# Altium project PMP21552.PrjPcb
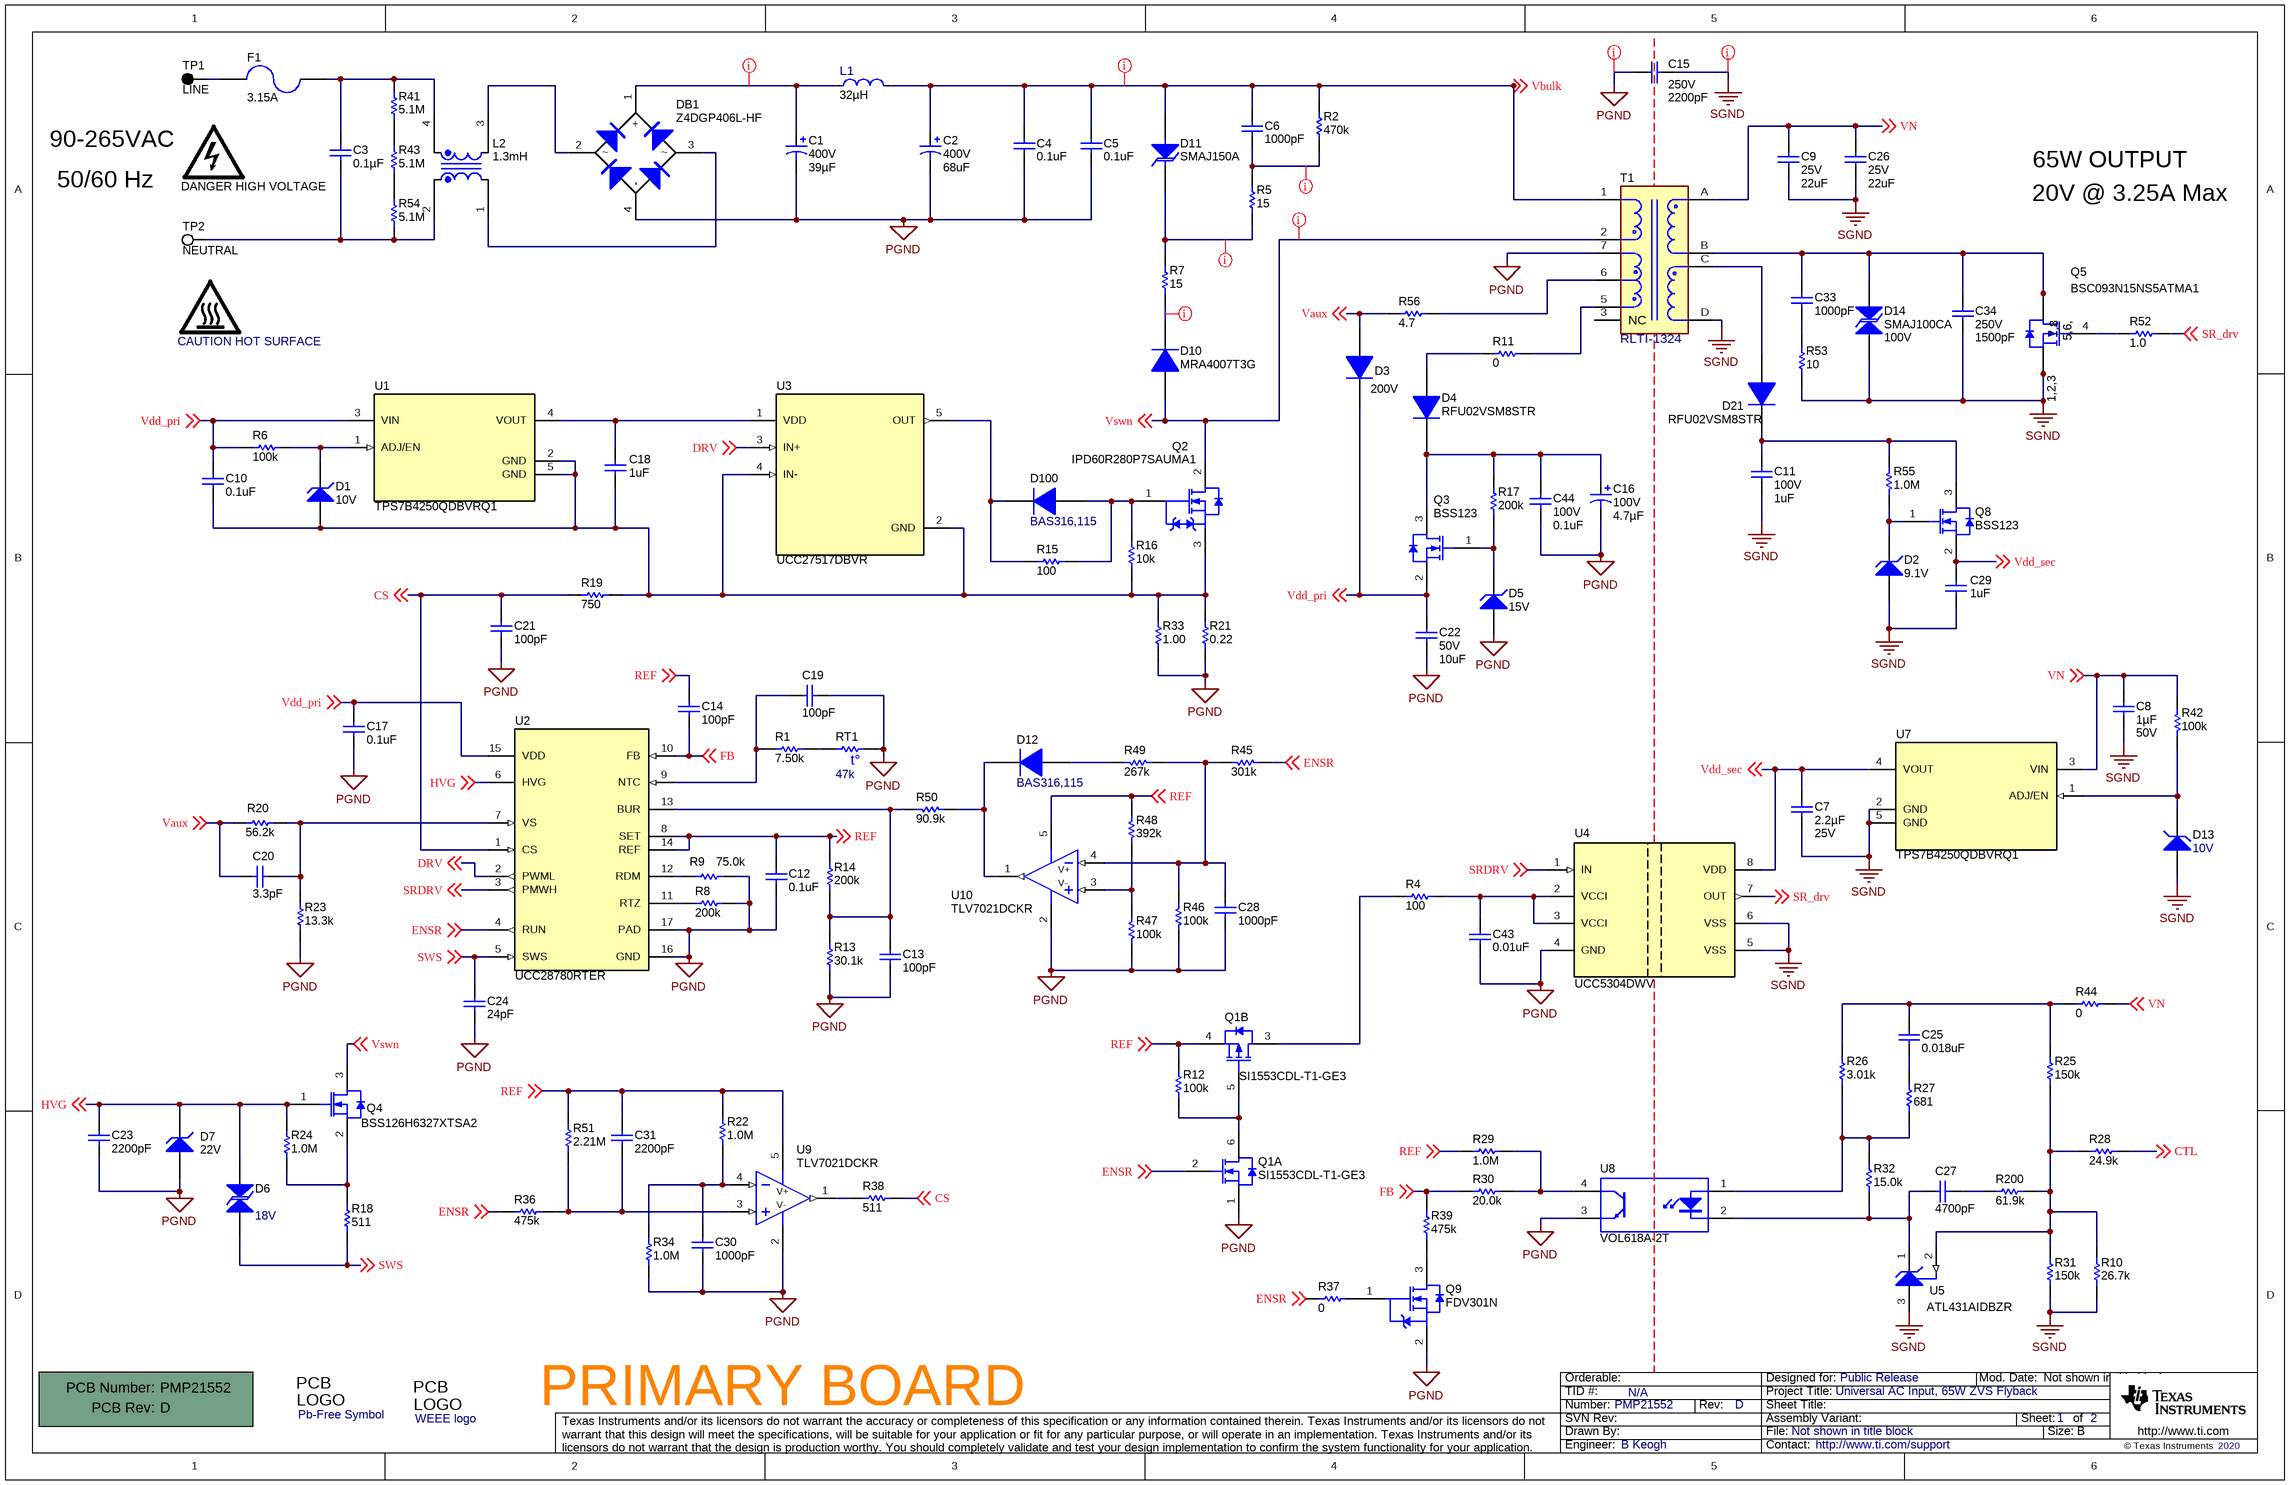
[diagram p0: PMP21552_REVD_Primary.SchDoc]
CopyrightYear: 2020; PCB_Layout: B King; PCB_Rev: D; PRJ_Customer: Public Release; PRJ_Engineer: B Keogh; PRJ_Number: PMP21552; PRJ_Title: Universal AC Input, 65W ZVS Flyback; SCH_Rev: D; TechSupport: http://www.ti.com/support; TID: N/A
2 sheets, 147 parts. Net scope: global (net labels, ports and power ports of the same name join across sheets).
Board file: PMP21552_REVD.PcbDoc
Sheets:
  PMP21552_REVD_Primary.SchDoc
  PMP21552_REVD_Secondary.SchDoc

## Sheet PMP21552_REVD_Primary.SchDoc
size 431 x 279 mm; Date: Not shown in title block; ApprovedBy: Not shown in title block; CheckedBy: Not shown in title block; Author: Not shown in title block; CompanyName: Not shown in title block; Engineer: Not shown in title block; Organization: Not shown in title block; Address1: Not shown in title block; Address2: Not shown in title block; Address3: Not shown in title block; Address4: Not shown in title block; DocumentNumber: 1; Revision: Use project parameter SCH_Rev; SheetNumber: 1; SheetTotal: 2; PageSetup: Record=PageOptions¦CenterHorizontal=True¦CenterVertical=True¦PrintScale=1.00¦XCorrection=1.00¦YCorrection=1.00¦PrintKind=0¦BorderSize=5000000¦LeftOffset=0¦BottomOffset=0¦Orientation=2¦PaperLength=1000¦PaperWidth=1000¦Scale=100¦PaperSource=15¦PrintQuality=600¦MediaType=1¦DitherType=10¦PaperKind=Letter¦PrintScaleMode=1

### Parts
!PCB1  Printed Circuit Board  (value not drawn)  (mechanical)
C1  VDC_V: 400V  ValueDisplayed: 39µF  [Chemi-Con_1450x2000]  (hidden comment: EKXJ401ELL390MU20S)
C2  VDC_V: 400V  ValueDisplayed: 68uF  [BXW_1800x2000]  (hidden comment: 400BXW68MEFC18X20)
C3  ValueDisplayed: 0.1µF  [WCAP-FTX2_1300x700x1300]  (hidden comment: 890324023023)
C4  ValueDisplayed: 0.1uF  [1210_280]  (hidden comment: C1210C104KBRAC7800)
C5  ValueDisplayed: 0.1uF  [1210_280]  (hidden comment: C1210C104KBRAC7800)
C6  ValueDisplayed: 1000pF  [1206L]  (hidden comment: GRM31BR72J102KW01L)
C7  Cap_F: 2.2µF  VDC_V: 25V  [0805_HV1]  (hidden comment: CGA4J3X7R1E225K125AB)
C8  Cap_F: 1µF  VDC_V: 50V  [0805_HV1]  (hidden comment: C2012X7R1H105K085AC)
C9  VDC_V: 25V  ValueDisplayed: 22uF  [1210_270L]  (hidden comment: GRM32ER71E226KE15L)
C10  ValueDisplayed: 0.1uF  [0402S]  (hidden comment: GRM155R71H104ME14D)
C11  VDC_V: 100V  ValueDisplayed: 1uF  [1206L]  (hidden comment: C3216X7R2A105M160AA)
C12  ValueDisplayed: 0.1uF  [0402S]  (hidden comment: C1005X7R1H104K050BB)
C13  ValueDisplayed: 100pF  [0402S]  (hidden comment: GRM1555C1H101JA01D)
C14  ValueDisplayed: 100pF  [0402S]  (hidden comment: GRM1555C1H101JA01D)
C15  VDC_V: 250V  ValueDisplayed: 2200pF  [DE1_900x400]  (hidden comment: DE1E3RA222MN4AN01F)
C16  VDC_V: 100V  ValueDisplayed: 4.7µF  [UPW_500x1100]  (hidden comment: UPS2A4R7MDD1TD)
C17  ValueDisplayed: 0.1uF  [0402S]  (hidden comment: GRM155R71H104ME14D)
C18  ValueDisplayed: 1uF  [0603S]  (hidden comment: C1608X7R1E105K080AB)
C19  ValueDisplayed: 100pF  [0402S]  (hidden comment: GRM1555C1H101JA01D)
C20  ValueDisplayed: 3.3pF  [0402S]  (hidden comment: GRM1555C1H3R3CA01D)
C21  ValueDisplayed: 100pF  [0402S]  (hidden comment: GRM1555C1H101JA01D)
C22  VDC_V: 50V  ValueDisplayed: 10uF  [1206_180]  (hidden comment: C3216X5R1H106K160AB)
C23  ValueDisplayed: 2200pF  [0402S]  (hidden comment: GRM155R71H222KA01D)
C24  ValueDisplayed: 24pF  [0402S]  (hidden comment: GRM1555C1H240JA01D)
C25  ValueDisplayed: 0.018uF  [0402S]  (hidden comment: GRM155R71H183KA12D)
C26  VDC_V: 25V  ValueDisplayed: 22uF  [1210_270L]  (hidden comment: GRM32ER71E226KE15L)
C27  ValueDisplayed: 4700pF  [0402S]  (hidden comment: GRM155R71H472KA01D)
C28  ValueDisplayed: 1000pF  [0402S]  (hidden comment: GRM155R71H102KA01D)
C29  ValueDisplayed: 1uF  [0603S]  (hidden comment: C1608X7R1E105K080AB)
C30  ValueDisplayed: 1000pF  [0402S]  (hidden comment: GRM155R71H102KA01D)
C31  ValueDisplayed: 2200pF  [0402S]  (hidden comment: GRM155R71H222KA01D)
C33  ValueDisplayed: 1000pF  [0805L]  (hidden comment: GRM21AR72E102KW01D)
C34  Value2: 250V  ValueDisplayed: 1500pF  [0805_HV1]  (hidden comment: GRM21AR72E152KW01D)
C43  ValueDisplayed: 0.01uF  [0402S]  (hidden comment: GRM155R71H103KA88D)
C44  VDC_V: 100V  ValueDisplayed: 0.1uF  [1206L]  (hidden comment: 12061C104JAT2A)
D1  value 10V  [SOD-323]  (hidden comment: MMSZ5240BS-7-F)
D2  value 9.1V  [SOD-323]  (hidden comment: BZT52C9V1S-7-F)
D3  value 200V  [SOD-123H]  (hidden comment: CSFMT104-HF)
D4  RFU02VSM8STR  [TUMD2SM]
D5  value 15V  [SOD-323]  (hidden comment: MMSZ5245BS-7-F)
D6  value 18V  [SOD-323-Bi]  (hidden comment: CDSOD323-T18C)
D7  value 22V  [SOD-523]  (hidden comment: BZT52C22T-7)
D10  MRA4007T3G  [SMA]
D11  SMAJ150A  [SMA]
D12  BAS316,115  [SOD-323]
D13  value 10V  [SOD-323]  (hidden comment: MMSZ5240BS-7-F)
D14  SMAJ100CA  value 100V  [SMA]
D21  RFU02VSM8STR  [TUMD2SM]
D100  BAS316,115  [SOD-323]
DB1  Z4DGP406L-HF  [Z4-D]
F1  Irating_A: 3.15A  [FUSE_392]  (hidden comment: 39213150000)
L1  Ind_H: 32µH  [FP-7447052_PTH_D10MM0-MFG]  (hidden comment: 7447052)
L2  ValueDisplayed: 1.3mH  [Renco_RLTI-1301]  (hidden comment: RLTI-1301)
LOGO1  DANGER HIGH VOLTAGE  [IEC_HighVoltage_Small]  (no BOM)
LOGO2  CAUTION HOT SURFACE  [IEC_HotSurface_Small]  (no BOM)
Logo3  Pb-Free Symbol  [Pb-Free_Overlay_Medium]  (no BOM)
Logo4  WEEE logo  [WEEE_Minimum]  (no BOM)
Q1  SI1553CDL-T1-GE3  [SOT-363]  (parts A,B of 2)
Q2  IPD60R280P7SAUMA1  [DPAK]
Q3  BSS123  [SOT-23L]
Q4  BSS126H6327XTSA2  [SOT-23L]
Q5  BSC093N15NS5ATMA1  [PG-TDSON-8]
Q8  BSS123  [SOT-23L]
Q9  FDV301N  [SOT-23L]
R1  ValueDisplayed: 7.50k  [0402L]  (hidden comment: CRCW04027K50FKED)
R2  ValueDisplayed: 470k  [0805_HV1]  (hidden comment: CRCW0805470KJNEA)
R4  ValueDisplayed: 100  [0402S]  (hidden comment: CRCW0402100RJNED)
R5  ValueDisplayed: 15  [0805_HV1]  (hidden comment: CRCW080515R0JNEA)
R6  ValueDisplayed: 100k  [0402L]  (hidden comment: RC0402FR-07100KL)
R7  ValueDisplayed: 15  [0805_HV1]  (hidden comment: CRCW080515R0JNEA)
R8  ValueDisplayed: 200k  [0402S]  (hidden comment: CRCW0402200KFKED)
R9  ValueDisplayed: 75.0k  [0402S]  (hidden comment: CRCW040275K0FKED)
R10  ValueDisplayed: 26.7k  [0402S]  (hidden comment: CRCW040226K7FKED)
R11  ValueDisplayed: 0  [0402S]  (hidden comment: CRCW04020000Z0ED)
R12  ValueDisplayed: 100k  [0402S]  (hidden comment: RC0402FR-07100KL)
R13  ValueDisplayed: 30.1k  [0402S]  (hidden comment: CRCW040230K1FKED)
R14  ValueDisplayed: 200k  [0402S]  (hidden comment: CRCW0402200KFKED)
R15  ValueDisplayed: 100  [0402]  (hidden comment: CRCW0402100RFKED)
R16  ValueDisplayed: 10k  [0402L]  (hidden comment: CRCW040210K0JNED)
R17  ValueDisplayed: 200k  [0402S]  (hidden comment: CRCW0402200KFKED)
R18  ValueDisplayed: 511  [0402S]  (hidden comment: CRCW0402511RFKED)
R19  ValueDisplayed: 750  [0402S]  (hidden comment: CRCW0402750RFKED)
R20  ValueDisplayed: 56.2k  [0402S]  (hidden comment: CRCW040256K2FKED)
R21  ValueDisplayed: 0.22  [1210L]  (hidden comment: MCR25JZHFLR220)
R22  ValueDisplayed: 1.0M  [0402S]  (hidden comment: CRCW04021M00JNED)
R23  ValueDisplayed: 13.3k  [0402S]  (hidden comment: CRCW040213K3FKED)
R24  ValueDisplayed: 1.0M  [0402S]  (hidden comment: CRCW04021M00JNED)
R25  ValueDisplayed: 150k  [0402S]  (hidden comment: ERJ-2RKF1503X)
R26  ValueDisplayed: 3.01k  [0402S]  (hidden comment: CRCW04023K01FKED)
R27  ValueDisplayed: 681  [0402L]  (hidden comment: CRCW0402681RFKED)
R28  ValueDisplayed: 24.9k  [0402S]  (hidden comment: CRCW040224K9FKED)
R29  ValueDisplayed: 1.0M  [0402S]  (hidden comment: CRCW04021M00JNED)
R30  ValueDisplayed: 20.0k  [0402S]  (hidden comment: CRCW040220K0FKED)
R31  ValueDisplayed: 150k  [0402S]  (hidden comment: ERJ-2RKF1503X)
R32  ValueDisplayed: 15.0k  [0402S]  (hidden comment: CRCW040215K0FKED)
R33  ValueDisplayed: 1.00  [0805_HV1]  (hidden comment: ERJ-6RQF1R0V)
R34  ValueDisplayed: 1.0M  [0402S]  (hidden comment: CRCW04021M00JNED)
R36  ValueDisplayed: 475k  [0402S]  (hidden comment: CRCW0402475KFKED)
R37  ValueDisplayed: 0  [0402S]  (hidden comment: RC0402JR-070RL)
R38  ValueDisplayed: 511  [0402S]  (hidden comment: CRCW0402511RFKED)
R39  ValueDisplayed: 475k  [0402S]  (hidden comment: CRCW0402475KFKED)
R41  ValueDisplayed: 5.1M  [0805_HV1]  (hidden comment: CRCW08055M10JNEA)
R42  ValueDisplayed: 100k  [0402S]  (hidden comment: RC0402FR-07100KL)
R43  ValueDisplayed: 5.1M  [0805_HV1]  (hidden comment: CRCW08055M10JNEA)
R44  ValueDisplayed: 0  [0402S]  (hidden comment: RC0402JR-070RL)
R45  ValueDisplayed: 301k  [0402S]  (hidden comment: CRCW0402301KFKED)
R46  ValueDisplayed: 100k  [0402S]  (hidden comment: RC0402FR-07100KL)
R47  ValueDisplayed: 100k  [0402S]  (hidden comment: RC0402FR-07100KL)
R48  ValueDisplayed: 392k  [0402S]  (hidden comment: CRCW0402392KFKED)
R49  ValueDisplayed: 267k  [0402S]  (hidden comment: CRCW0402267KFKED)
R50  ValueDisplayed: 90.9k  [0402S]  (hidden comment: CRCW040290K9FKED)
R51  ValueDisplayed: 2.21M  [0402S]  (hidden comment: CRCW04022M21FKED)
R52  ValueDisplayed: 1.0  [0402S]  (hidden comment: CRCW04021R00JNED)
R53  ValueDisplayed: 10  [1206L]  (hidden comment: CRCW120610R0JNEA)
R54  ValueDisplayed: 5.1M  [0805_HV1]  (hidden comment: CRCW08055M10JNEA)
R55  ValueDisplayed: 1.0M  [0402S]  (hidden comment: CRCW04021M00JNED)
R56  ValueDisplayed: 4.7  [0402S]  (hidden comment: CRCW04024R70JNED)
R200  ValueDisplayed: 61.9k  [0402S]  (hidden comment: CRCW040261K9FKED)
RT1  value 47k  [0603S]  (hidden comment: NCP18WB473J03RB)
T1  RLTI-1324  [FP-RLTI-1324_PTH_0IN980_0IN766-MFG]
TP1  LINE  [Keystone5011]
TP2  NEUTRAL  [Keystone5012]
U1  TPS7B4250QDBVRQ1  [DBV0005A_N]
U2  UCC28780RTER  [RTE0016C]
U3  UCC27517DBVR  [DBV0005A_N]
U4  UCC5304DWV  [DWV0008A]
U5  ATL431AIDBZR  [DBZ0003A_L]
U7  TPS7B4250QDBVRQ1  [DBV0005A_L]
U8  VOL618A-2T  [SOP254P1020X230-4]
U9  TLV7021DCKR  [DCK0005A_N]
U10  TLV7021DCKR  [DCK0005A_N]

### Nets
PGND: C1.2(-) C2.2(-) C4.1 C5.1 C12.2 C13.1 C15.2 C16.2(-) C17.2 C19.1 C21.1 C22.2 C23.2 C24.1 C28.2 C30.2 C43.1 C44.2 D5.2(A) D7.2(A) DB1.4(-) Q1.1(S) Q9.2(S) R8.1 R9.2 R13.1 R21.1 R23.1 R33.1 R34.2 R46.2 R47.2 RT1.2 T1.7 U2.16(GND) U2.17(PAD) U4.4(GND) U8.3(E) U9.2(V-) U10.2(V-)
SGND: C7.2 C8.2 C9.2 C11.2 C15.1 C26.2 C29.1 C34.2 D2.2(A) D13.2(A) D14.1 Q5.1(S) Q5.2(S) Q5.3(S) R10.2 R31.2 R53.1 T1.D U4.5(VSS) U4.6(VSS) U5.3(ANODE) U7.2(GND) U7.5(GND)
CS: C21.2 R19.1 R38.2 U2.1(CS) ; off-sheet CS
CTL: R28.1 ; off-sheet CTL
DRV: U2.2(PWML) U3.3(IN+) ; off-sheet DRV
ENSR: Q1.2(G) R36.1 R37.2 R45.1 U2.4(RUN) ; off-sheet ENSR
FB: C14.1 R30.1 R39.2 U2.10(FB) ; off-sheet FB
HVG: C23.1 D6.2 D7.1(K) Q4.1(G) R24.2 U2.6(HVG) ; off-sheet HVG
REF: C12.1 C14.2 C31.1 Q1.4(S) R12.1 R14.2 R22.2 R29.2 R48.2 R51.2 U2.8(SET) U2.14(REF) U9.5(V+) U10.5(V+) ; off-sheet REF
SR_drv: R52.1 U4.7(OUT) ; off-sheet SR_drv
SRDRV: U2.3(PMWH) U4.1(IN) ; off-sheet SRDRV
SWS: C24.2 D6.1 R18.1 U2.5(SWS) ; off-sheet SWS
Vaux: C20.1 D3.2(A) R20.2 R56.1 ; off-sheet Vaux
Vbulk: C2.1(+) C4.2 C5.2 C6.1 D11.2(A) L1.2 R2.2 T1.1 ; off-sheet Vbulk
Vdd_pri: C10.1 C17.1 C22.1 D3.1(K) Q3.2(S) R6.2 U1.3(VIN) U2.15(VDD) ; off-sheet Vdd_pri
Vdd_sec: C7.1 C29.2 Q8.2(S) U4.8(VDD) U7.4(VOUT) ; off-sheet Vdd_sec
VN: C8.1 C9.1 C26.1 R42.1 R44.1 T1.A U7.3(VIN) ; off-sheet VN
Vswn: D10.2(A) Q2.2(D) Q4.3(D) T1.2 ; off-sheet Vswn
NetC1_1: C1.1(+) DB1.1(+) L1.1
NetC3_1: C3.1 F1.1 L2.4 R41.2
NetC3_2: C3.2 L2.2 R54.1 TP2.1
NetC6_2: C6.2 R2.1 R5.2
NetC10_2: C10.2 C18.1 D1.2(A) Q2.3(S) R16.1 R19.2 R21.2 R33.2 U1.2(GND) U1.5(GND) U3.2(GND) U3.4(IN-)
NetC11_1: C11.1 D21.1(K) Q8.3(D) R55.1
NetC13_2: C13.2 R13.2 R14.1 R50.2 U2.13(BUR)
NetC16_1: C16.1(+) C44.1 D4.1(K) Q3.3(D) R17.1
NetC18_2: C18.2 U1.4(VOUT) U3.1(VDD)
NetC19_2: C19.2 R1.1 U2.9(NTC)
NetC20_2: C20.2 R20.1 R23.2 U2.7(VS)
NetC25_1: C25.1 R25.2 R26.2 R44.2
NetC25_2: C25.2 R27.2
NetC27_1: C27.1 R200.1
NetC27_2: C27.2 R32.1 U5.1(CATHODE) U8.2(K)
NetC28_1: C28.1 R45.2 R46.1 R49.1 U10.4(IN-)
NetC30_1: C30.1 R22.1 R34.1 U9.4(IN-)
NetC31_2: C31.2 R36.2 R51.1 U9.3(IN+)
NetC33_1: C33.1 R53.2
NetC33_2: C33.2 C34.1 D14.2 Q5.5(D) Q5.6(D) Q5.7(D) Q5.8(D) Q5.9(D) T1.B
NetC43_2: C43.2 R4.1 U4.2(VCCI) U4.3(VCCI)
NetD1_1: D1.1(K) R6.1 U1.1(ADJ/EN)
NetD2_1: D2.1(K) Q8.1(G) R55.2
NetD4_2: D4.2(A) R11.2
NetD5_1: D5.1(K) Q3.1(G) R17.2
NetD10_1: D10.1(K) R7.1
NetD11_1: D11.1(K) R5.1 R7.2
NetD12_1: D12.1(K) R50.1 U10.1(OUT)
NetD12_2: D12.2(A) R49.2
NetD13_1: D13.1(K) R42.2 U7.1(ADJ/EN)
NetD21_2: D21.2(A) T1.C
NetD100_1: D100.1(K) R15.1 U3.5(OUT)
NetD100_2: D100.2(A) Q2.1(G) R15.2 R16.2
NetDB1_2: DB1.2 L2.3
NetDB1_3: DB1.3 L2.1
NetF1_2: F1.2 TP1.1
NetQ1_3: Q1.3(D) R4.2
NetQ1_5: Q1.5(G) Q1.6(D) R12.2
NetQ4_2: Q4.2(S) R18.2 R24.1
NetQ5_4: Q5.4(G) R52.2
NetQ9_1: Q9.1(G) R37.1
NetQ9_3: Q9.3(D) R39.1
NetR1_2: R1.2 RT1.1
NetR8_2: R8.2 U2.11(RTZ)
NetR9_1: R9.1 U2.12(RDM)
NetR10_1: R10.1 R25.1 R28.2 R31.1 R200.2 U5.2(REF)
NetR11_1: R11.1 T1.5
NetR26_1: R26.1 R27.1 R32.2 U8.1(A)
NetR29_1: R29.1 R30.2 U8.4(C)
NetR38_1: R38.1 U9.1(OUT)
NetR41_1: R41.1 R43.2
NetR43_1: R43.1 R54.2
NetR47_1: R47.1 R48.1 U10.3(IN+)
NetR56_2: R56.2 T1.6

Not connected (* = marked no-connect by the designer): T1 3(NC)

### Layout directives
net class HV: NetC1_1, NetC6_2, NetD10_1, NetD11_1, Vbulk, Vswn
net class Primary: PGND
net class Secondary: SGND

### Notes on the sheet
- 90-265VAC
- 65W OUTPUT
- 50/60 Hz
- 20V @ 3.25A Max
- PRIMARY BOARD

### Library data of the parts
!PCB1 = CMP-0003618-2: Manufacturer: Any; PartNumber: PMP21552; CompType: PCB
C1 = CMP-0067531-1: CAP, AL, 39 µF, 400 V, +/- 20%, AEC-Q200 Grade 2, TH; Manufacturer: Chemi-Con; TaMin_C: -40°C; Polarized: Y; SizeAreaWB_mm2: 272.25; Value1: Unknown; U/M: EA; Value: 39uF; TaMax_C: 105°C; SizeZ_mm: 21.5; SizeX_mm: 14.5; Cap_Case: 14.5X20mm; SizeArea_mm2: 210.25; CompType: Capacitor; IRMS_A: 385mA; AEC Grade: 2; AEC Category: Q200
C2 = CMP-0009972-1: CAP, AL, 68 uF, 400 V, +/- 20%, TH; Manufacturer: Rubycon; TaMin_C: -40°C; Polarized: Y; SizeAreaWB_mm2: 400; Value1: Unknown; U/M: EA; Value: 68uF; TaMax_C: 105°C; SizeZ_mm: 22; SizeX_mm: 18; Cap_Case: 18x20mm; SizeArea_mm2: 324; CompType: Capacitor; AEC Qualified: N; Cap_F: 68µF; IRMS_A: 530mA; AEC Category: Q200
C3 = CMP-0081647-1: CAP, Film, 0.1 µF,  V,+/- 10%, TH; Manufacturer: Wurth Elektronik; Cap_F: 100nF; SizeAreaWB_mm2: 135; SizeArea_mm2: 91; AEC Qualified: N; AEC Category: Q200; Value: 0.1uF; TaMax_C: 105°C; SizeZ_mm: 13.5; TaMin_C: -40°C; SizeY_mm: 7; SizeX_mm: 13; Cap_Case: 13x7x13mm
C4 C5 = CMP-0009076-1: CAP, CERM, 0.1 uF, 630 V, +/- 10%, X7R, 1210; Manufacturer: Kemet; Polarized: N; CompType: Capacitor; Value: 0.1uF; U/M: EA; Cap_F: 100nF; Value1: Unknown; VDC_V: 630V; TaMin_C: -55°C; TaMax_C: 125°C; Cap_Case: 1210; SizeArea_mm2: 8; SizeAreaWB_mm2: 14.7; SizeX_mm: 3.2; SizeY_mm: 2.5; SizeZ_mm: 2.8; AEC Category: Q200
C6 = GRM31BR72J102KW01L: CAP, CERM, 1000 pF, 630 V,+/- 10%, X7R, 1206; Manufacturer: MuRata; Polarized: N; CompType: Capacitor; Value: 1000pF; U/M: EA; Cap_F: 0.000000001; Tolerance_%: 10; VDC_V: 630; Value2: 630V; TaMin_C: -55; TaMax_C: 125; Cap_Case: 1206; SizeArea_mm2: 5.12; SizeAreaWB_mm2: 10.92; SizeX_mm: 3.2; SizeY_mm: 1.6; SizeZ_mm: 1.35; AEC Category: Q200; Green_Lifecycle: Not Set; Green_REACh: Incomplete
C7 = CMP-0007975-2: CAP, CERM, 2.2 uF, 25 V, +/- 10%, X7R, AEC-Q200 Grade 1, 0805; Manufacturer: TDK; TaMin_C: -55°C; Polarized: N; SizeAreaWB_mm2: 6.75; Value1: Unknown; U/M: EA; Value: 2.2uF; TaMax_C: 125°C; SizeZ_mm: 1.45; SizeX_mm: 2; SizeY_mm: 1.25; Cap_Case: 0805; SizeArea_mm2: 2.5; AEC Qualified: Y; AEC Grade: 1; AEC Category: Q200
C8 = CMP-0007872-2: CAP, CERM, 1 uF, 50 V, +/- 10%, X7R, 0805; Manufacturer: TDK; TaMin_C: -55°C; Polarized: N; SizeAreaWB_mm2: 6.75; Value1: Unknown; U/M: EA; Value: 1uF; TaMax_C: 125°C; SizeZ_mm: 1.45; SizeX_mm: 2; SizeY_mm: 1.25; Cap_Case: 0805; SizeArea_mm2: 2.5; AEC Category: Q200
C9 C26 = CMP-0009224-2: CAP, CERM, 22 uF, 25 V, +/- 10%, X7R, 1210; Manufacturer: MuRata; TaMin_C: -55°C; Polarized: N; SizeAreaWB_mm2: 14.7; Value1: Unknown; U/M: EA; Value: 22uF; TaMax_C: 125°C; SizeZ_mm: 2.7; SizeX_mm: 3.2; SizeY_mm: 2.5; Cap_Case: 1210; SizeArea_mm2: 8; Cap_F: 22µF; AEC Category: Q200
C10 C17 = CMP-0006675-2: CAP, CERM, 0.1 uF, 50 V, +/- 20%, X7R, 0402; Manufacturer: MuRata; TaMin_C: -55°C; Polarized: N; SizeAreaWB_mm2: 3; Value1: Unknown; U/M: EA; Value: 0.1uF; TaMax_C: 125°C; SizeZ_mm: 0.6; SizeX_mm: 1; SizeY_mm: 0.5; Cap_Case: 0402; Value2: 50V; Cap_F: 100nF; AEC Category: Q200
C11 = CMP-0008711-2: CAP, CERM, 1 uF, 100 V, +/- 20%, X7R, 1206; Manufacturer: TDK; TaMin_C: -55°C; Polarized: N; SizeAreaWB_mm2: 10.92; Value1: Unknown; U/M: EA; Value: 1uF; TaMax_C: 125°C; SizeZ_mm: 1.35; SizeX_mm: 3.2; SizeY_mm: 1.6; Cap_Case: 1206; SizeArea_mm2: 5.12; Cap_F: 1µF; AEC Category: Q200
C12 = CMP-0006297-2: CAP, CERM, 0.1 uF, 50 V, +/- 10%, X7R, 0402; Manufacturer: TDK; TaMin_C: -55°C; ESR_ohm: 0.039064; Polarized: N; SizeAreaWB_mm2: 3; Value1: 0.039064 ohm; U/M: EA; Value: 0.1uF; TaMax_C: 125°C; SizeZ_mm: 0.6; SizeX_mm: 1; SizeY_mm: 0.5; Cap_Case: 0402; Value2: 50V; CompType: Capacitor; Cap_F: 100nF; IRMS_A: 8.14669dA; AEC Category: Q200
C13 C14 C19 C21 = CMP-0006410-2: CAP, CERM, 100 pF, 50 V, +/- 5%, C0G/NP0, 0402; Manufacturer: MuRata; TaMin_C: -55°C; Polarized: N; SizeAreaWB_mm2: 3; Value1: Unknown; U/M: EA; Value: 100pF; TaMax_C: 125°C; SizeZ_mm: 0.6; SizeX_mm: 1; SizeY_mm: 0.5; Cap_Case: 0402; Value2: 50V; AEC Category: Q200
C15 = CMP-0086279-1: CAP CER 2200PF 250V RAD; Manufacturer: MuRata; SizeX_mm: 10.6; CompType: Capacitor; AEC Qualified: N; SizeY_mm: 4; TempCo: E; U/M: EA; AEC Category: Q200; TaMax_C: 125°C; Cap_Case: 9x4mm; Tolerance_%: 20%; Polarized: Y; SizeZ_mm: 12; TaMin_C: -40°C; SizeArea_mm2: 42.4; SizeAreaWB_mm2: 75.6; Cap_F: 2.2nF
C16 = CMP-0084595-1: CAP, AL, 4.7 µF, 100 V, +/- 20%, TH; Manufacturer: Nichicon; Cap_Case: 5x11mm; SizeArea_mm2: 25; Value: 4.7uF; Polarized: Y; SizeAreaWB_mm2: 49; CompType: Capacitor; SizeX_mm: 5; TaMin_C: -55°C; AEC Category: Q200; SizeZ_mm: 12.5; TaMax_C: 105°C; AEC Qualified: N; U/M: EA
C18 C29 = CMP-0007040-4: CAP, CERM, 1 uF, 25 V, +/- 10%, X7R, 0603; Manufacturer: TDK; Polarized: N; CompType: Capacitor; Value: 1uF; U/M: EA; Cap_F: 1µF; Value1: Unknown; VDC_V: 25V; TaMin_C: -55°C; TaMax_C: 125°C; Cap_Case: 0603; AEC Category: Q200; SizeArea_mm2: 1.28; SizeAreaWB_mm2: 4.68; SizeX_mm: 1.6; SizeY_mm: 0.8; SizeZ_mm: 1
C20 = CMP-0006462-2: CAP, CERM, 3.3 pF, 50 V, +/- 5%, C0G/NP0, 0402; Manufacturer: MuRata; TaMin_C: -55°C; Polarized: N; SizeAreaWB_mm2: 3; Value1: Unknown; U/M: EA; Value: 3.3pF; TaMax_C: 125°C; SizeZ_mm: 0.6; SizeX_mm: 1; SizeY_mm: 0.5; Cap_Case: 0402; Value2: 50V; CompType: Capacitor; AEC Category: Q200
C22 = CMP-0008658-2: CAP, CERM, 10 uF, 50 V, +/- 10%, X5R, 1206; Manufacturer: TDK; TaMin_C: -55°C; ESR_ohm: 2.229m; Polarized: N; SizeAreaWB_mm2: 10.92; Value1: 0.002229 ohm; U/M: EA; Value: 10uF; TaMax_C: 85°C; SizeZ_mm: 1.8; SizeX_mm: 3.2; SizeY_mm: 1.6; SizeArea_mm2: 5.12; CompType: Capacitor; Cap_F: 10µF; IRMS_A: 4.85932A; AEC Category: Q200
C23 C31 = CMP-0006683-2: CAP, CERM, 2200 pF, 50 V, +/- 10%, X7R, 0402; Manufacturer: MuRata; TaMin_C: -55°C; Polarized: N; SizeAreaWB_mm2: 3; Value1: Unknown; U/M: EA; Value: 2200pF; TaMax_C: 125°C; SizeZ_mm: 0.6; SizeX_mm: 1; SizeY_mm: 0.5; Cap_Case: 0402; Value2: 50V; CompType: Capacitor; Cap_F: 2.2nF; AEC Category: Q200
C24 = CMP-0006441-2: CAP, CERM, 24 pF, 50 V, +/- 5%, C0G/NP0, 0402; Manufacturer: MuRata; TaMin_C: -55°C; Polarized: N; SizeAreaWB_mm2: 3; Value1: Unknown; U/M: EA; Value: 24pF; TaMax_C: 125°C; SizeZ_mm: 0.6; SizeX_mm: 1; SizeY_mm: 0.5; Cap_Case: 0402; Value2: 50V; CompType: Capacitor; AEC Category: Q200
C25 = CMP-0006681-2: CAP, CERM, 0.018 uF, 50 V, +/- 10%, X7R, 0402; Manufacturer: MuRata; TaMin_C: -55°C; Polarized: N; SizeAreaWB_mm2: 3; Value1: Unknown; U/M: EA; TaMax_C: 125°C; SizeZ_mm: 0.6; SizeX_mm: 1; SizeY_mm: 0.5; Cap_Case: 0402; Value2: 50V; Cap_F: 18nF; AEC Category: Q200
C27 = CMP-0006692-2: CAP, CERM, 4700 pF, 50 V, +/- 10%, X7R, 0402; Manufacturer: MuRata; TaMin_C: -55°C; Polarized: N; SizeAreaWB_mm2: 3; Value1: Unknown; U/M: EA; Value: 4700pF; TaMax_C: 125°C; SizeZ_mm: 0.6; SizeX_mm: 1; SizeY_mm: 0.5; Cap_Case: 0402; Value2: 50V; Cap_F: 4.7nF; AEC Category: Q200
C28 C30 = CMP-0006673-2: CAP, CERM, 1000 pF, 50 V, +/- 10%, X7R, 0402; Manufacturer: MuRata; TaMin_C: -55°C; Polarized: N; SizeAreaWB_mm2: 3; Value1: Unknown; U/M: EA; Value: 1000pF; TaMax_C: 125°C; SizeZ_mm: 0.6; SizeX_mm: 1; SizeY_mm: 0.5; Cap_Case: 0402; Value2: 50V; Cap_F: 1nF; AEC Category: Q200
C33 = CMP-0008251-2: CAP, CERM, 1000 pF, 250 V, +/- 10%, X7R, 0805; Manufacturer: MuRata; TaMin_C: -55°C; Polarized: N; SizeAreaWB_mm2: 6.75; Value1: Unknown; U/M: EA; Value: 1000pF; TaMax_C: 125°C; SizeZ_mm: 1.45; SizeX_mm: 2; SizeY_mm: 1.25; Cap_Case: 0805; Value2: 250V; SizeArea_mm2: 2.5; Cap_F: 1nF; AEC Category: Q200
C34 = CMP-0008252-2: CAP, CERM, 1500 pF, 250 V, +/- 10%, X7R, 0805; Manufacturer: MuRata; TaMin_C: -55°C; Polarized: N; SizeAreaWB_mm2: 6.75; Value1: Unknown; U/M: EA; Value: 1500pF; TaMax_C: 125°C; SizeZ_mm: 1.45; SizeX_mm: 2; SizeY_mm: 1.25; Cap_Case: 0805; SizeArea_mm2: 2.5; Cap_F: 1.5nF; AEC Category: Q200
C43 = CMP-0006674-2: CAP, CERM, 0.01 uF, 50 V, +/- 10%, X7R, 0402; Manufacturer: MuRata; TaMin_C: -55°C; Polarized: N; SizeAreaWB_mm2: 3; Value1: Unknown; U/M: EA; Value: 0.01uF; TaMax_C: 125°C; SizeZ_mm: 0.6; SizeX_mm: 1; SizeY_mm: 0.5; Cap_Case: 0402; Value2: 50V; Cap_F: 10nF; AEC Category: Q200
C44 = CMP-0008487-2: CAP, CERM, 0.1 uF, 100 V, +/- 5%, X7R, 1206; Manufacturer: AVX; TaMin_C: -55°C; ESR_ohm: 0.037; Polarized: N; SizeAreaWB_mm2: 10.92; Value1: 0.037 ohm; U/M: EA; Value: 0.1uF; TaMax_C: 125°C; SizeZ_mm: 1.35; SizeX_mm: 3.2; SizeY_mm: 1.6; Cap_Case: 1206; SizeArea_mm2: 5.12; CompType: Capacitor; Cap_F: 100nF; AEC Category: Q200
D1 D13 = CMP-0005829-1: Diode, Zener, 10 V, 200 mW, SOD-323; Manufacturer: Diodes Inc.; Power_W: 200mW; SizeAreaWB_mm2: 8.695; Value1: 0.2W; RJA_CperW: 350; U/M: EA; SizeZ_mm: 1; SizeX_mm: 2.7; SizeY_mm: 1.35; SizeArea_mm2: 3.645; AEC Category: Q101
D2 = BZT52C9V1S-7-F: Diode, Zener, 9.1 V, 200 mW, SOD-323; Manufacturer: Diodes Inc.; SymbolCreator: a0412235; U/M: EA; Power_W: 0.2; Vz_V: 9.1; Value1: 0.2W; RJA_CperW: 625; SizeAreaWB_mm2: 8.695; SizeArea_mm2: 3.645; SizeX_mm: 2.7; SizeY_mm: 1.35; SizeZ_mm: 1; AEC Category: Q101
D3 = CMP-0029199-1: Diode, Superfast Rectifier, 200 V, 1 A, 3.5x1.6mm; Manufacturer: Comchip Technology; U/M: EA; Vf_V: 9.5dV; Value1: 1A; Value2: 0.95V; TJmax_C: 150°C; SizeAreaWB_mm2: 11.7; SizeArea_mm2: 5.6; SizeX_mm: 3.5; SizeY_mm: 1.6; SizeZ_mm: 1; AEC Category: Q101; AEC Qualified: N
D4 D21 = CMP-0077868-1: Diode, Standard Recovery Rectifier, 800 V, .2 A, 2x1.4mm; Manufacturer: Rohm; SizeAreaWB_mm2: 8.4; Vr_V: 800V; SizeArea_mm2: 3.5; AEC Qualified: N; TJmax_C: 150°C; AEC Category: Q101; Value: 800V; SizeZ_mm: 0.8; Io_A: 2dA; Vf_V: 2.2V; SizeY_mm: 1.4; Value1: .2A; SizeX_mm: 2.5
D5 = CMP-0005833-2: Diode, Zener, 15 V, 200 mW, SOD-323; Manufacturer: Diodes Inc.; Power_W: 200mW; SizeAreaWB_mm2: 8.695; Value1: 0.2W; RJA_CperW: 350; U/M: EA; SizeZ_mm: 1; SizeX_mm: 2.7; SizeY_mm: 1.35; SizeArea_mm2: 3.645; AEC Category: Q101
D6 = CMP-0005822-3: Diode, TVS, Bi, 18 V, SOD-323; Manufacturer: Bourns; SizeArea_mm2: 3.645; SizeY_mm: 1.35; VRWM: 24V; Ppk: 350W; SizeZ_mm: 1; SizeX_mm: 2.7; SizeAreaWB_mm2: 8.695; AEC Category: Q101
D7 = CMP-0005884-3: Diode, Zener, 22 V, 300 mW, SOD-523; Manufacturer: Diodes Inc.; U/M: EA; Power_W: 300mW; Value1: 0.3W; RJA_CperW: 417; SizeAreaWB_mm2: 5.13; SizeArea_mm2: 1.53; SizeX_mm: 1.7; SizeY_mm: 0.9; SizeZ_mm: 0.65; AEC Category: Q101
D10 = CMP-0077082-1: Diode, Standard Recovery Rectifier, 1000 V, 1 A, AEC-Q101, SMA; Manufacturer: ON Semiconductor; SizeAreaWB_mm2: 37.3428; Vr_V: 1kV; SizeArea_mm2: 16.3228; AEC Qualified: Y; TJmax_C: 175°C; AEC Category: Q101; Value: 1000V; SizeZ_mm: 2.87; Green_REACh: Passed; Io_A: 1A; Vf_V: 1.1V; SizeY_mm: 2.92; Green_Lifecycle: Active; U/M: EA; SizeX_mm: 5.59; RJC_CperW: 16.2
D11 = CMP-0084982-1: Diode, TVS, Uni, 150 V, 243 Vc, 400 W, 1.6 A, SMA; Manufacturer: Littelfuse; Vc: 243V; Ipp: 1.6A; RJA_CperW: 120; AEC Qualified: N; Value: 150V; Ppk: 400W; AEC Category: Q101; SizeArea_mm2: 16.3228; SizeAreaWB_mm2: 37.3428; SizeZ_mm: 2.87; Vbr_Max: 185V; SizeX_mm: 5.59; SizeY_mm: 2.92; Vbr_Min: 167V
D12 D100 = CMP-0029006-2: Diode, Ultrafast, 100 V, 0.25 A, SOD-323; Manufacturer: Nexperia; SizeY_mm: 1.35; Value1: 0.25A; SizeAreaWB_mm2: 8.695; SizeZ_mm: 1; Io_A: 250mA; Value2: 1.4V; SizeX_mm: 2.7; Green_REACh: Incomplete; TJmax_C: 150°C; Green_Lifecycle: Not Set; Vr_V: 100V; AEC Category: Q101; Value: 100V; SizeArea_mm2: 3.645
D14 = CMP-0005466-2: Diode, TVS, Bi, 100 V, SMA; Manufacturer: Littelfuse; Power_W: 3.3W; SizeAreaWB_mm2: 37.3428; RJA_CperW: 120; U/M: EA; SizeZ_mm: 2.87; SizeX_mm: 5.59; SizeY_mm: 2.92; SizeArea_mm2: 16.3228; AEC Category: Q101
DB1 = Z4DGP406L-HF: Diode, P-N-Bridge, 600 V, 4 A, Z4-D; Manufacturer: Comchip Technology; U/M: EA; Vf_V: 0.95; Value: 600V; Value1: 4A; Value2: 0.95V; Io_A: 4; Vr_V: 600; TJmax_C: 175; SizeAreaWB_mm2: 126.25; SizeArea_mm2: 85.05; SizeX_mm: 10.5; SizeY_mm: 8.1; SizeZ_mm: 1.55; AEC Category: Q101; AEC Qualified: N; Green_Lifecycle: Not Set; Green_REACh: Incomplete
F1 = CMP-0003561-2: Fuse, 3.15 A, 250VAC/VDC, TH; Manufacturer: Littelfuse; VAC_V: 250V
L1 = CMP-0087546-1: WE-FI Leaded Toroidal Line Choke; Manufacturer: Wurth; SizeZ_mm: 10mm; Irms: 2.6A; DCR_ohm: 0.045; AEC Qualified: No; Symbol Name: SYM-7447052
L2 = CMP-0086351-1: Coupled inductor, 1.3 mH, 0.035 ohm, TH; Manufacturer: Renco Electronics; SizeY_mm: 15.24; DCR_ohm: 0.035; AEC Category: Q200; AEC Qualified: N; SizeX_mm: 9.906; Value: 1.3mH; SizeAreaWB_mm2: 205.25944; SizeZ_mm: 18.415; SizeArea_mm2: 150.96744
LOGO1 = IEC_HighVoltage: IEC 61010-1 High Voltage Warning; SymbolCreator: a0412235
LOGO2 = CMP-0074837-1: IEC 61010-1 Hot Surface Warning; SymbolCreator: a0412235
Logo3 = CMP-0074839-1: SymbolCreator: a0412235
Logo4 = CMP-0074769-1
Q1 = CMP-0000173-4: MOSFET, 2-CH, N/P-CH, 20 V, 0.7 A, SOT-363; Alternate Manufacturer: None; Manufacturer: Vishay-Siliconix; SizeArea_mm2: 4.84; IdsMax_A: 700mA; QgTyp_nC: 1.2; ChType: N; ChMode: Enhancement; Value: 20V; Vgs_V: 12V; Value1: 0.3; SizeX_mm: 2.2; AEC Category: Q101; SizeAreaWB_mm2: 10.24; Rdson45_ohm: 0.39; Value2: 1.2 nC; SizeZ_mm: 1.1
Q2 = CMP-0079238-2: MOSFET, N-CH, 600 V, 12 A, DPAK; Alternate Manufacturer: None; Manufacturer: Infineon Technologies; ChType: N; Vgs_V: 20V; ChMode: Enhancement; Value1: ? ohm; SizeAreaWB_mm2: 101.7114; SizeZ_mm: 2.29; QgTyp_nC: 18; VdsMax_V: 600V; SizeArea_mm2: 64.8114; SizeY_mm: 6.54; AEC Category: Q101; Value: 600V; SizeX_mm: 9.91; IdsMax_A: 12A; Value2: 18 nC
Q3 Q8 = BSS123: MOSFET, N-CH, 100 V, 0.17 A, SOT-23; Manufacturer: Fairchild Semiconductor; Alternate Manufacturer: None; U/M: EA; ChType: N; Value: 100V; VdsMax_V: 100; Value1: 10 ohm; Rdson45_ohm: 10; Value2: 1.8 nC; QgTyp_nC: 1.8; Vgs_V: 20; IdsMax_A: 0.17; SizeAreaWB_mm2: 14; SizeArea_mm2: 7.5; SizeX_mm: 2.5; SizeY_mm: 3; SizeZ_mm: 1.1; AEC Category: Q101; Green_Lifecycle: Active; Green_REACh: Passed
Q4 = CMP-0067574-1: MOSFET, N-CH, 600 V, 0.021 A, AEC-Q101, SOT-23; Manufacturer: Infineon Technologies; Alternate Manufacturer: None; U/M: EA; ChType: N; Value: 600V; Value1: ? ohm; Value2: 1.4 nC; QgTyp_nC: 1.4; Vgs_V: 20V; IdsMax_A: 21mA; SizeAreaWB_mm2: 14.0; SizeArea_mm2: 7.5; SizeX_mm: 2.5; SizeY_mm: 3.0; SizeZ_mm: 1.1; AEC Category: Q101; AEC Qualified: Y
Q5 = CMP-0001046-2: MOSFET, N-CH, 150 V, 87 A, PG-TDSON-8; Alternate Manufacturer: None; Manufacturer: Infineon Technologies; SizeZ_mm: 1.12; ChType: N; Value2: 33 nC; VdsMax_V: 150V; SizeX_mm: 5.99; SizeY_mm: 4.9; Vgs_V: 20V; QgTyp_nC: 33; Value: 150V; SizeArea_mm2: 29.351; AEC Category: Q101; IdsMax_A: 87A; SizeAreaWB_mm2: 55.131; U/M: EA
Q9 = CMP-0000281-1: MOSFET, N-CH, 25 V, 0.22 A, SOT-23; Alternate Manufacturer: None; Manufacturer: Fairchild Semiconductor; SizeZ_mm: 1.1; ChType: N; Value2: 0.49 nC; VdsMax_V: 25V; SizeX_mm: 2.5; SizeY_mm: 3; Vgs_V: 8V; Value: 25V; Rdson45_ohm: 4; SizeArea_mm2: 7.5; AEC Category: Q101; IdsMax_A: 2.2dA; SizeAreaWB_mm2: 14; U/M: EA; QgTyp_nC: 0.49
R1 = CMP-0026555-2: RES, 7.50 k, 1%, 0.063 W, AEC-Q200 Grade 0, 0402; Manufacturer: Vishay-Dale; Power_W: 63mW; TempCo: 100 ppm/C; Value_Code: 7k50; Value: 7.50k; EIA_Code: E96; Res_ohm: 7.5k; SizeX_mm: 1; SizeY_mm: 0.5; SizeZ_mm: 0.6; Value2: 0.063W; AEC Qualified: Y; VDC_V: 50V; AEC Category: Q200; AEC Grade: 0
R2 = CMP-0020554-3: RES, 470 k, 5%, 0.125 W, AEC-Q200 Grade 0, 0805; Manufacturer: Vishay-Dale; Power_W: 125mW; TempCo: 200 ppm/C; Value: 470k; EIA_Code: E24; SizeX_mm: 2; SizeY_mm: 1.25; SizeZ_mm: 1.45; Value2: 0.125W; SizeArea_mm2: 2.5; AEC Qualified: Y; VDC_V: 150V; AEC Category: Q200; AEC Grade: 0
R4 = CMP-0026824-3: RES, 100, 5%, 0.063 W, AEC-Q200 Grade 0, 0402; Manufacturer: Vishay-Dale; Power_W: 63mW; TempCo: 200 ppm/C; Value_Code: 100R; Value: 100; EIA_Code: E24; SizeX_mm: 1; SizeY_mm: 0.5; SizeZ_mm: 0.6; Value2: 0.063W; AEC Qualified: Y; VDC_V: 50V; AEC Category: Q200; AEC Grade: 0
R5 R7 = CMP-0020464-3: RES, 15, 5%, 0.125 W, AEC-Q200 Grade 0, 0805; Manufacturer: Vishay-Dale; Power_W: 125mW; TempCo: 200 ppm/C; Value_Code: 15R0; Value: 15; EIA_Code: E24; SizeX_mm: 2; SizeY_mm: 1.25; SizeZ_mm: 1.45; Value2: 0.125W; SizeArea_mm2: 2.5; AEC Qualified: Y; VDC_V: 150V; AEC Category: Q200; AEC Grade: 0
R6 R12 R42 R46 R47 = CMP-0026721-1: RES, 100 k, 1%, 0.0625 W, 0402; Manufacturer: Yageo America; Power_W: 62.5mW; TempCo: 100 ppm/C; U/M: EA; Value: 100k; EIA_Code: E96; SizeX_mm: 1; SizeY_mm: 0.5; SizeZ_mm: 0.6; CompType: Resistor; AEC Qualified: N; VDC_V: 50V; AEC Category: Q200
R8 R14 R17 = CMP-0026158-2: RES, 200 k, 1%, 0.063 W, AEC-Q200 Grade 0, 0402; Manufacturer: Vishay-Dale; Power_W: 63mW; TempCo: 100 ppm/C; Value: 200k; EIA_Code: E96; SizeX_mm: 1; SizeY_mm: 0.5; SizeZ_mm: 0.6; Value2: 0.063W; AEC Qualified: Y; VDC_V: 50V; AEC Category: Q200; AEC Grade: 0
R9 = CMP-0026543-2: RES, 75.0 k, 1%, 0.063 W, AEC-Q200 Grade 0, 0402; Manufacturer: Vishay-Dale; Power_W: 63mW; TempCo: 100 ppm/C; Value_Code: 75k0; Value: 75.0k; EIA_Code: E96; Res_ohm: 75k; SizeX_mm: 1; SizeY_mm: 0.5; SizeZ_mm: 0.6; Value2: 0.063W; AEC Qualified: Y; VDC_V: 50V; AEC Category: Q200; AEC Grade: 0
R10 = CMP-0026208-2: RES, 26.7 k, 1%, 0.063 W, AEC-Q200 Grade 0, 0402; Manufacturer: Vishay-Dale; Power_W: 63mW; TempCo: 100 ppm/C; Value_Code: 26k7; Value: 26.7k; EIA_Code: E96; SizeX_mm: 1; SizeY_mm: 0.5; SizeZ_mm: 0.6; Value2: 0.063W; AEC Qualified: Y; VDC_V: 50V; AEC Category: Q200; AEC Grade: 0
R11 = CMP-0026822-3: RES, 0, 5%, 0.063 W, AEC-Q200 Grade 0, 0402; Manufacturer: Vishay-Dale; Power_W: 63mW; TempCo: 200 ppm/C; Value_Code: 0000; Value: 0; EIA_Code: E24; SizeX_mm: 1; SizeY_mm: 0.5; SizeZ_mm: 0.6; Value2: 0.063W; CompType: Resistor; AEC Qualified: Y; VDC_V: 50V; AEC Category: Q200
R13 = CMP-0026284-2: RES, 30.1 k, 1%, 0.063 W, AEC-Q200 Grade 0, 0402; Manufacturer: Vishay-Dale; Power_W: 63mW; TempCo: 100 ppm/C; Value_Code: 30k1; Value: 30.1k; EIA_Code: E96; SizeX_mm: 1; SizeY_mm: 0.5; SizeZ_mm: 0.6; Value2: 0.063W; AEC Qualified: Y; VDC_V: 50V; AEC Category: Q200; AEC Grade: 0
R15 = CMP-0025951-3: RES, 100, 1%, 0.063 W, AEC-Q200 Grade 0, 0402; Manufacturer: Vishay-Dale; Power_W: 63mW; TempCo: 100 ppm/C; Value_Code: 100R; Value: 100; EIA_Code: E96; SizeX_mm: 1; SizeY_mm: 0.5; SizeZ_mm: 0.6; Value2: 0.063W; AEC Qualified: Y; VDC_V: 50V; AEC Category: Q200; AEC Grade: 0
R16 = CMP-0026825-5: RES, 10 k, 5%, 0.063 W, AEC-Q200 Grade 0, 0402; Manufacturer: Vishay-Dale; Power_W: 63mW; TempCo: 200 ppm/C; Value_Code: 10k0; Value: 10k; EIA_Code: E24; SizeX_mm: 1; SizeY_mm: 0.5; SizeZ_mm: 0.6; Value2: 0.063W; CompType: Resistor; AEC Qualified: Y; VDC_V: 50V; AEC Category: Q200; AEC Grade: 0
R18 R38 = CMP-0026436-2: RES, 511, 1%, 0.063 W, AEC-Q200 Grade 0, 0402; Manufacturer: Vishay-Dale; Power_W: 63mW; TempCo: 100 ppm/C; Value_Code: 511R; Value: 511; EIA_Code: E96; SizeX_mm: 1; SizeY_mm: 0.5; SizeZ_mm: 0.6; Value2: 0.063W; AEC Qualified: Y; VDC_V: 50V; AEC Category: Q200; AEC Grade: 0
R19 = CMP-0026542-2: RES, 750, 1%, 0.063 W, AEC-Q200 Grade 0, 0402; Manufacturer: Vishay-Dale; Power_W: 63mW; TempCo: 100 ppm/C; Value_Code: 750R; Value: 750; EIA_Code: E96; SizeX_mm: 1; SizeY_mm: 0.5; SizeZ_mm: 0.6; Value2: 0.063W; AEC Qualified: Y; VDC_V: 50V; AEC Grade: 0; AEC Category: Q200
R20 = CMP-0026453-2: RES, 56.2 k, 1%, 0.063 W, AEC-Q200 Grade 0, 0402; Manufacturer: Vishay-Dale; Power_W: 63mW; TempCo: 100 ppm/C; Value_Code: 56k2; Value: 56.2k; EIA_Code: E96; SizeX_mm: 1; SizeY_mm: 0.5; SizeZ_mm: 0.6; Value2: 0.063W; CompType: Resistor; AEC Qualified: Y; VDC_V: 50V; AEC Category: Q200; AEC Grade: 0
R21 = CMP-0015175-1: RES, 0.22, 1%, 0.5 W, 1210; Manufacturer: Rohm; Power_W: 500mW; TempCo: 200 ppm/C; SizeAreaWB_mm2: 14.7; Value_Code: R220; U/M: EA; Value: 0.22; EIA_Code: E96; SizeX_mm: 3.2; SizeY_mm: 2.5; SizeZ_mm: 1.35; Value2: 0.5W; SizeArea_mm2: 8; VDC_V: 0V; AEC Category: Q200
R22 R24 R29 R34 = CMP-0026859-2: RES, 1.0 M, 5%, 0.063 W, AEC-Q200 Grade 0, 0402; Manufacturer: Vishay-Dale; CompType: Resistor; Value: 1.0Meg; Res_ohm: 1M; Value_Code: 1M00; Power_W: 63mW; Value2: 0.063W; VDC_V: 50V; TempCo: 200 ppm/C; SizeArea_mm2: 0.5; SizeX_mm: 1; SizeZ_mm: 0.6; EIA_Code: E24; AEC Category: Q200; AEC Qualified: Y; AEC Grade: 0
R23 = CMP-0026004-3: RES, 13.3 k, 1%, 0.063 W, AEC-Q200 Grade 0, 0402; Manufacturer: Vishay-Dale; Power_W: 63mW; TempCo: 100 ppm/C; Value_Code: 13k3; Value: 13.3k; EIA_Code: E96; SizeX_mm: 1; SizeY_mm: 0.5; SizeZ_mm: 0.6; Value2: 0.063W; CompType: Resistor; AEC Qualified: Y; VDC_V: 50V; AEC Category: Q200; AEC Grade: 0
R25 R31 = CMP-0026669-1: RES, 150 k, 1%, 0.1 W, AEC-Q200 Grade 0, 0402; Manufacturer: Panasonic; Power_W: 100mW; TempCo: 100 ppm/C; U/M: EA; Value: 150k; EIA_Code: E96; SizeX_mm: 1; SizeY_mm: 0.5; SizeZ_mm: 0.6; Value2: 0.1W; CompType: Resistor; AEC Qualified: Y; VDC_V: 50V; AEC Grade: 0; AEC Category: Q200
R26 = CMP-0026329-2: RES, 3.01 k, 1%, 0.063 W, AEC-Q200 Grade 0, 0402; Manufacturer: Vishay-Dale; Power_W: 63mW; TempCo: 100 ppm/C; Value_Code: 3k01; Value: 3.01k; EIA_Code: E96; SizeX_mm: 1; SizeY_mm: 0.5; SizeZ_mm: 0.6; Value2: 0.063W; CompType: Resistor; AEC Qualified: Y; VDC_V: 50V; AEC Category: Q200; AEC Grade: 0
R27 = CMP-0026505-2: RES, 681, 1%, 0.063 W, AEC-Q200 Grade 0, 0402; Manufacturer: Vishay-Dale; Power_W: 63mW; TempCo: 100 ppm/C; Value_Code: 681R; Value: 681; EIA_Code: E96; SizeX_mm: 1; SizeY_mm: 0.5; SizeZ_mm: 0.6; Value2: 0.063W; AEC Qualified: Y; VDC_V: 50V; AEC Category: Q200; AEC Grade: 0
R28 = CMP-0026196-2: RES, 24.9 k, 1%, 0.063 W, AEC-Q200 Grade 0, 0402; Manufacturer: Vishay-Dale; Power_W: 63mW; TempCo: 100 ppm/C; Value_Code: 24k9; Value: 24.9k; EIA_Code: E96; SizeX_mm: 1; SizeY_mm: 0.5; SizeZ_mm: 0.6; Value2: 0.063W; CompType: Resistor; AEC Qualified: Y; VDC_V: 50V; AEC Category: Q200; AEC Grade: 0
R30 = CMP-0026162-2: RES, 20.0 k, 1%, 0.063 W, AEC-Q200 Grade 0, 0402; Manufacturer: Vishay-Dale; Power_W: 63mW; TempCo: 100 ppm/C; Value_Code: 20k0; Value: 20.0k; EIA_Code: E96; Res_ohm: 20k; SizeX_mm: 1; SizeY_mm: 0.5; SizeZ_mm: 0.6; Value2: 0.063W; AEC Qualified: Y; VDC_V: 50V; AEC Category: Q200; AEC Grade: 0
R32 = CMP-0026027-3: RES, 15.0 k, 1%, 0.063 W, AEC-Q200 Grade 0, 0402; Manufacturer: Vishay-Dale; Power_W: 63mW; TempCo: 100 ppm/C; Value_Code: 15k0; Value: 15.0k; EIA_Code: E96; Res_ohm: 15k; SizeX_mm: 1; SizeY_mm: 0.5; SizeZ_mm: 0.6; Value2: 0.063W; CompType: Resistor; AEC Qualified: Y; VDC_V: 50V; AEC Category: Q200; AEC Grade: 0
R33 = CMP-0021824-3: RES, 1.00, 1%, 0.125 W, AEC-Q200 Grade 0, 0805; Manufacturer: Panasonic; Power_W: 125mW; TempCo: 200 ppm/C; Value_Code: 1R00; Value: 1.00; EIA_Code: E96; Res_ohm: 1; SizeX_mm: 2; SizeY_mm: 1.25; SizeZ_mm: 1.45; Value2: 0.125W; SizeArea_mm2: 2.5; AEC Qualified: Y; AEC Category: Q200; AEC Grade: 0; SizeAreaWB_mm2: 6.75
R36 R39 = CMP-0026393-2: RES, 475 k, 1%, 0.063 W, AEC-Q200 Grade 0, 0402; Manufacturer: Vishay-Dale; Power_W: 63mW; TempCo: 100 ppm/C; Value: 475k; EIA_Code: E96; SizeX_mm: 1; SizeY_mm: 0.5; SizeZ_mm: 0.6; Value2: 0.063W; AEC Qualified: Y; VDC_V: 50V; AEC Category: Q200; AEC Grade: 0
R37 R44 = CMP-0027004-2: RES, 0, 5%, 0.063 W, 0402; Manufacturer: Yageo America; Power_W: 63mW; TempCo: 200 ppm/C; Value_Code: 0000; U/M: EA; Value: 0; EIA_Code: E24; SizeX_mm: 1; SizeY_mm: 0.5; SizeZ_mm: 0.6; Value2: 0.063W; CompType: Resistor; VDC_V: 50V; AEC Category: Q200
R41 R43 R54 = CMP-0020574-3: RES, 5.1 M, 5%, 0.125 W, AEC-Q200 Grade 0, 0805; Manufacturer: Vishay-Dale; Power_W: 125mW; TempCo: 200 ppm/C; Value_Code: 5M10; Value: 5.1Meg; EIA_Code: E24; SizeX_mm: 2; SizeY_mm: 1.25; SizeZ_mm: 1.45; Value2: 0.125W; SizeArea_mm2: 2.5; AEC Qualified: Y; VDC_V: 150V; AEC Category: Q200; AEC Grade: 0
R45 = CMP-0026280-2: RES, 301 k, 1%, 0.063 W, AEC-Q200 Grade 0, 0402; Manufacturer: Vishay-Dale; Power_W: 63mW; TempCo: 100 ppm/C; Value: 301k; EIA_Code: E96; SizeX_mm: 1; SizeY_mm: 0.5; SizeZ_mm: 0.6; Value2: 0.063W; AEC Qualified: Y; VDC_V: 50V; AEC Category: Q200; AEC Grade: 0
R48 = CMP-0026325-2: RES, 392 k, 1%, 0.063 W, AEC-Q200 Grade 0, 0402; Manufacturer: Vishay-Dale; Power_W: 63mW; TempCo: 100 ppm/C; Value: 392k; EIA_Code: E96; SizeX_mm: 1; SizeY_mm: 0.5; SizeZ_mm: 0.6; Value2: 0.063W; AEC Qualified: Y; VDC_V: 50V; AEC Category: Q200; AEC Grade: 0
R49 = CMP-0026205-2: RES, 267 k, 1%, 0.063 W, AEC-Q200 Grade 0, 0402; Manufacturer: Vishay-Dale; Power_W: 63mW; TempCo: 100 ppm/C; Value: 267k; EIA_Code: E96; SizeX_mm: 1; SizeY_mm: 0.5; SizeZ_mm: 0.6; Value2: 0.063W; AEC Qualified: Y; VDC_V: 50V; AEC Category: Q200; AEC Grade: 0
R50 = CMP-0026605-2: RES, 90.9 k, 1%, 0.063 W, AEC-Q200 Grade 0, 0402; Manufacturer: Vishay-Dale; Power_W: 63mW; TempCo: 100 ppm/C; Value_Code: 90k9; Value: 90.9k; EIA_Code: E96; SizeX_mm: 1; SizeY_mm: 0.5; SizeZ_mm: 0.6; Value2: 0.063W; AEC Qualified: Y; VDC_V: 50V; AEC Category: Q200; AEC Grade: 0
R51 = CMP-0026249-2: RES, 2.21 M, 1%, 0.063 W, AEC-Q200 Grade 0, 0402; Manufacturer: Vishay-Dale; Power_W: 63mW; TempCo: 100 ppm/C; Value_Code: 2M21; Value: 2.21Meg; EIA_Code: E96; SizeX_mm: 1; SizeY_mm: 0.5; SizeZ_mm: 0.6; Value2: 0.063W; AEC Qualified: Y; VDC_V: 50V; AEC Category: Q200; AEC Grade: 0
R52 = CMP-0026866-3: RES, 1.0, 5%, 0.063 W, AEC-Q200 Grade 0, 0402; Manufacturer: Vishay-Dale; Value: 1.0; Res_ohm: 1; Value_Code: 1R00; Power_W: 63mW; Value2: 0.063W; VDC_V: 50V; TempCo: 200 ppm/C; SizeArea_mm2: 0.5; SizeZ_mm: 0.6; EIA_Code: E24; AEC Category: Q200; AEC Qualified: Y; AEC Grade: 0
R53 = CMP-0018578-3: RES, 10, 5%, 0.25 W, AEC-Q200 Grade 0, 1206; Manufacturer: Vishay-Dale; Power_W: 250mW; TempCo: 200 ppm/C; Value_Code: 10R0; Value: 10; EIA_Code: E24; SizeX_mm: 3.2; SizeY_mm: 1.6; SizeZ_mm: 1.35; Value2: 0.25W; SizeArea_mm2: 5.12; AEC Qualified: Y; VDC_V: 200V; AEC Category: Q200; AEC Grade: 0
R55 = CRCW04021M00JNED: RES, 1.0 M, 5%, 0.063 W, 0402; Manufacturer: Vishay-Dale; CompType: Resistor; Value: 1.0Meg; Res_ohm: 1000000; Value_Code: 1M00; Tolerance_%: 5; Power_W: 0.063; Value2: 0.063W; VDC_V: 50; TempCo: 200 ppm/C; SizeArea_mm2: 0.5; SizeX_mm: 1; SizeZ_mm: 0.6; EIA_Code: E24; U/M: EA; AEC Category: Q200; Green_Lifecycle: Active; Green_REACh: Passed
R56 = CMP-0026942-3: RES, 4.7, 5%, 0.063 W, AEC-Q200 Grade 0, 0402; Manufacturer: Vishay-Dale; Power_W: 63mW; TempCo: 200 ppm/C; Value_Code: 4R70; Value: 4.7; EIA_Code: E24; SizeX_mm: 1; SizeY_mm: 0.5; SizeZ_mm: 0.6; Value2: 0.063W; AEC Qualified: Y; VDC_V: 50V; AEC Category: Q200; AEC Grade: 0
R200 = CMP-0026490-2: RES, 61.9 k, 1%, 0.063 W, AEC-Q200 Grade 0, 0402; Manufacturer: Vishay-Dale; Power_W: 63mW; TempCo: 100 ppm/C; Value_Code: 61k9; Value: 61.9k; EIA_Code: E96; SizeX_mm: 1; SizeY_mm: 0.5; SizeZ_mm: 0.6; Value2: 0.063W; AEC Qualified: Y; VDC_V: 50V; AEC Category: Q200; AEC Grade: 0
RT1 = CMP-0002523-3: Thermistor NTC, 47k ohm, 5%, 0603; Manufacturer: MuRata; TaMax_C: 125°C; SizeX_mm: 1.6; SizeY_mm: 0.8; TaMin_C: -40°C; Power_W: 100mW; SizeZ_mm: 1; SizeArea_mm2: 1.28; SizeAreaWB_mm2: 4.68; U/M: EA
T1 = CMP-0087465-1: MODIFIED RLTI-1324 TRANSFORMER; Manufacturer: Renco Electronics; AEC Qualified: No; SizeZ_mm: 0.66inch; DCR_ohm: 0.1Ω; Ind_H: 110µH; Ns1toNp: 2.5:0.5:1:0.5:1
TP1 = CMP-0055148-1: Test Point, Multipurpose, Black, TH; Manufacturer: Keystone; PartNumber: 5011; CNHeader: FALSE; Green_Lifecycle: Active; Green_REACh: Passed; ContactFinish: Silver; CT: TRUE
TP2 = CMP-0055149-1: Test Point, Multipurpose, White, TH; Manufacturer: Keystone; PartNumber: 5012; CNHeader: FALSE; Green_Lifecycle: Active; Green_REACh: Passed; ContactFinish: Silver; CT: TRUE
U1 U7 = CMP-0066933-1: 50-mA 40-V Voltage-Tracking LDO With 5-mV Tracking Tolerance, DBV0005A (SOT-23-5); Alternate Manufacturer: Texas Instruments; SizeAreaWB_mm2: 14.82; U/M: EA; SizeZ_mm: 1.45; SizeX_mm: 2.8; SizeY_mm: 2.9; SizeArea_mm2: 8.12; CompType: IC
U2 = CMP-0860425-1: High Frequency Active Clamp Flyback Controller, RTE0016C (WQFN-16); Alternate Manufacturer: Texas Instruments; SizeArea_mm2: 9; SizeZ_mm: 0.8; SizeX_mm: 3; AEC Category: Q200; SizeAreaWB_mm2: 16; CompType: IC; AEC Qualified: N
U3 = CMP-0066947-1: 4A/4A Single Channel High-speed Low-side Gate Driver, DBV0005A (SOT-23-5); Alternate PartNumber: UCC27517DBVT; Alternate Manufacturer: Texas Instruments; Green_Lifecycle: Active; SizeAreaWB_mm2: 14.82; Green_REACh: Passed; U/M: EA; SizeZ_mm: 1.45; SizeX_mm: 2.8; SizeY_mm: 2.9; SizeArea_mm2: 8.12; CompType: IC
U4 = CMP-0860377-2: 4-A/6-A, Single-Channel Reinforced Isolation Gate Driver with High Noise Immunity, DWV0008A (SOIC-8); Manufacturer: Texas Instruments; SizeX_mm: 11.5; SizeArea_mm2: 67.275; SizeAreaWB_mm2: 105.975; CompType: IC; SizeZ_mm: 2.8; SizeY_mm: 5.85; AEC Category: Q200; AEC Qualified: N
U5 = CMP-0066199-1: 2.5V Low Iq Adjustable Precision Shunt Regulator, DBZ0003A (SOT-23-3); Manufacturer: Texas Instruments; SizeArea_mm2: 7.5; SizeAreaWB_mm2: 14.0; SizeX_mm: 2.5; SizeY_mm: 3.0; SizeZ_mm: 1.12; CompType: IC; U/M: EA
U8 = CMP-0006160-3: Optocoupler, 5 kV, 63-125% CTR, SMT; Manufacturer: Vishay-Semiconductor; CTR (Max): 125%; SizeAreaWB_mm2: 74.42; CTR (Min): 63%; SizeZ_mm: 2.3; SizeX_mm: 10.2; SizeY_mm: 4.1; SizeArea_mm2: 41.82; Voltage_Isolation_Vrms: 5kV
U9 U10 = CMP-0085889-2: Small-Size Micropower Low-Voltage Comparator, DCK0005A (SOT-SC70-5); Manufacturer: Texas Instruments; Alternate PartNumber: TLV7021DCKT; SizeAreaWB_mm2: 9.3; SizeY_mm: 2; Rating: Catalog; SizeZ_mm: 1.1; SizeX_mm: 2.1; CompType: IC; AEC Qualified: N; SizeArea_mm2: 4.2; AEC Category: Q200

## Sheet PMP21552_REVD_Secondary.SchDoc
size 431 x 279 mm; Date: Not shown in title block; ApprovedBy: Not shown in title block; CheckedBy: Not shown in title block; Author: Not shown in title block; CompanyName: Not shown in title block; Engineer: Not shown in title block; Organization: Not shown in title block; Address1: Not shown in title block; Address2: Not shown in title block; Address3: Not shown in title block; Address4: Not shown in title block; DocumentNumber: 2; Revision: Use project parameter SCH_Rev; SheetNumber: 2; SheetTotal: 2; PageSetup: Record=PageOptions¦CenterHorizontal=True¦CenterVertical=True¦PrintScale=1.00¦XCorrection=1.00¦YCorrection=1.00¦PrintKind=0¦BorderSize=5000000¦LeftOffset=0¦BottomOffset=0¦Orientation=2¦PaperLength=1000¦PaperWidth=1000¦Scale=100¦PaperSource=15¦PrintQuality=600¦MediaType=1¦DitherType=10¦PaperKind=Letter¦PrintScaleMode=1
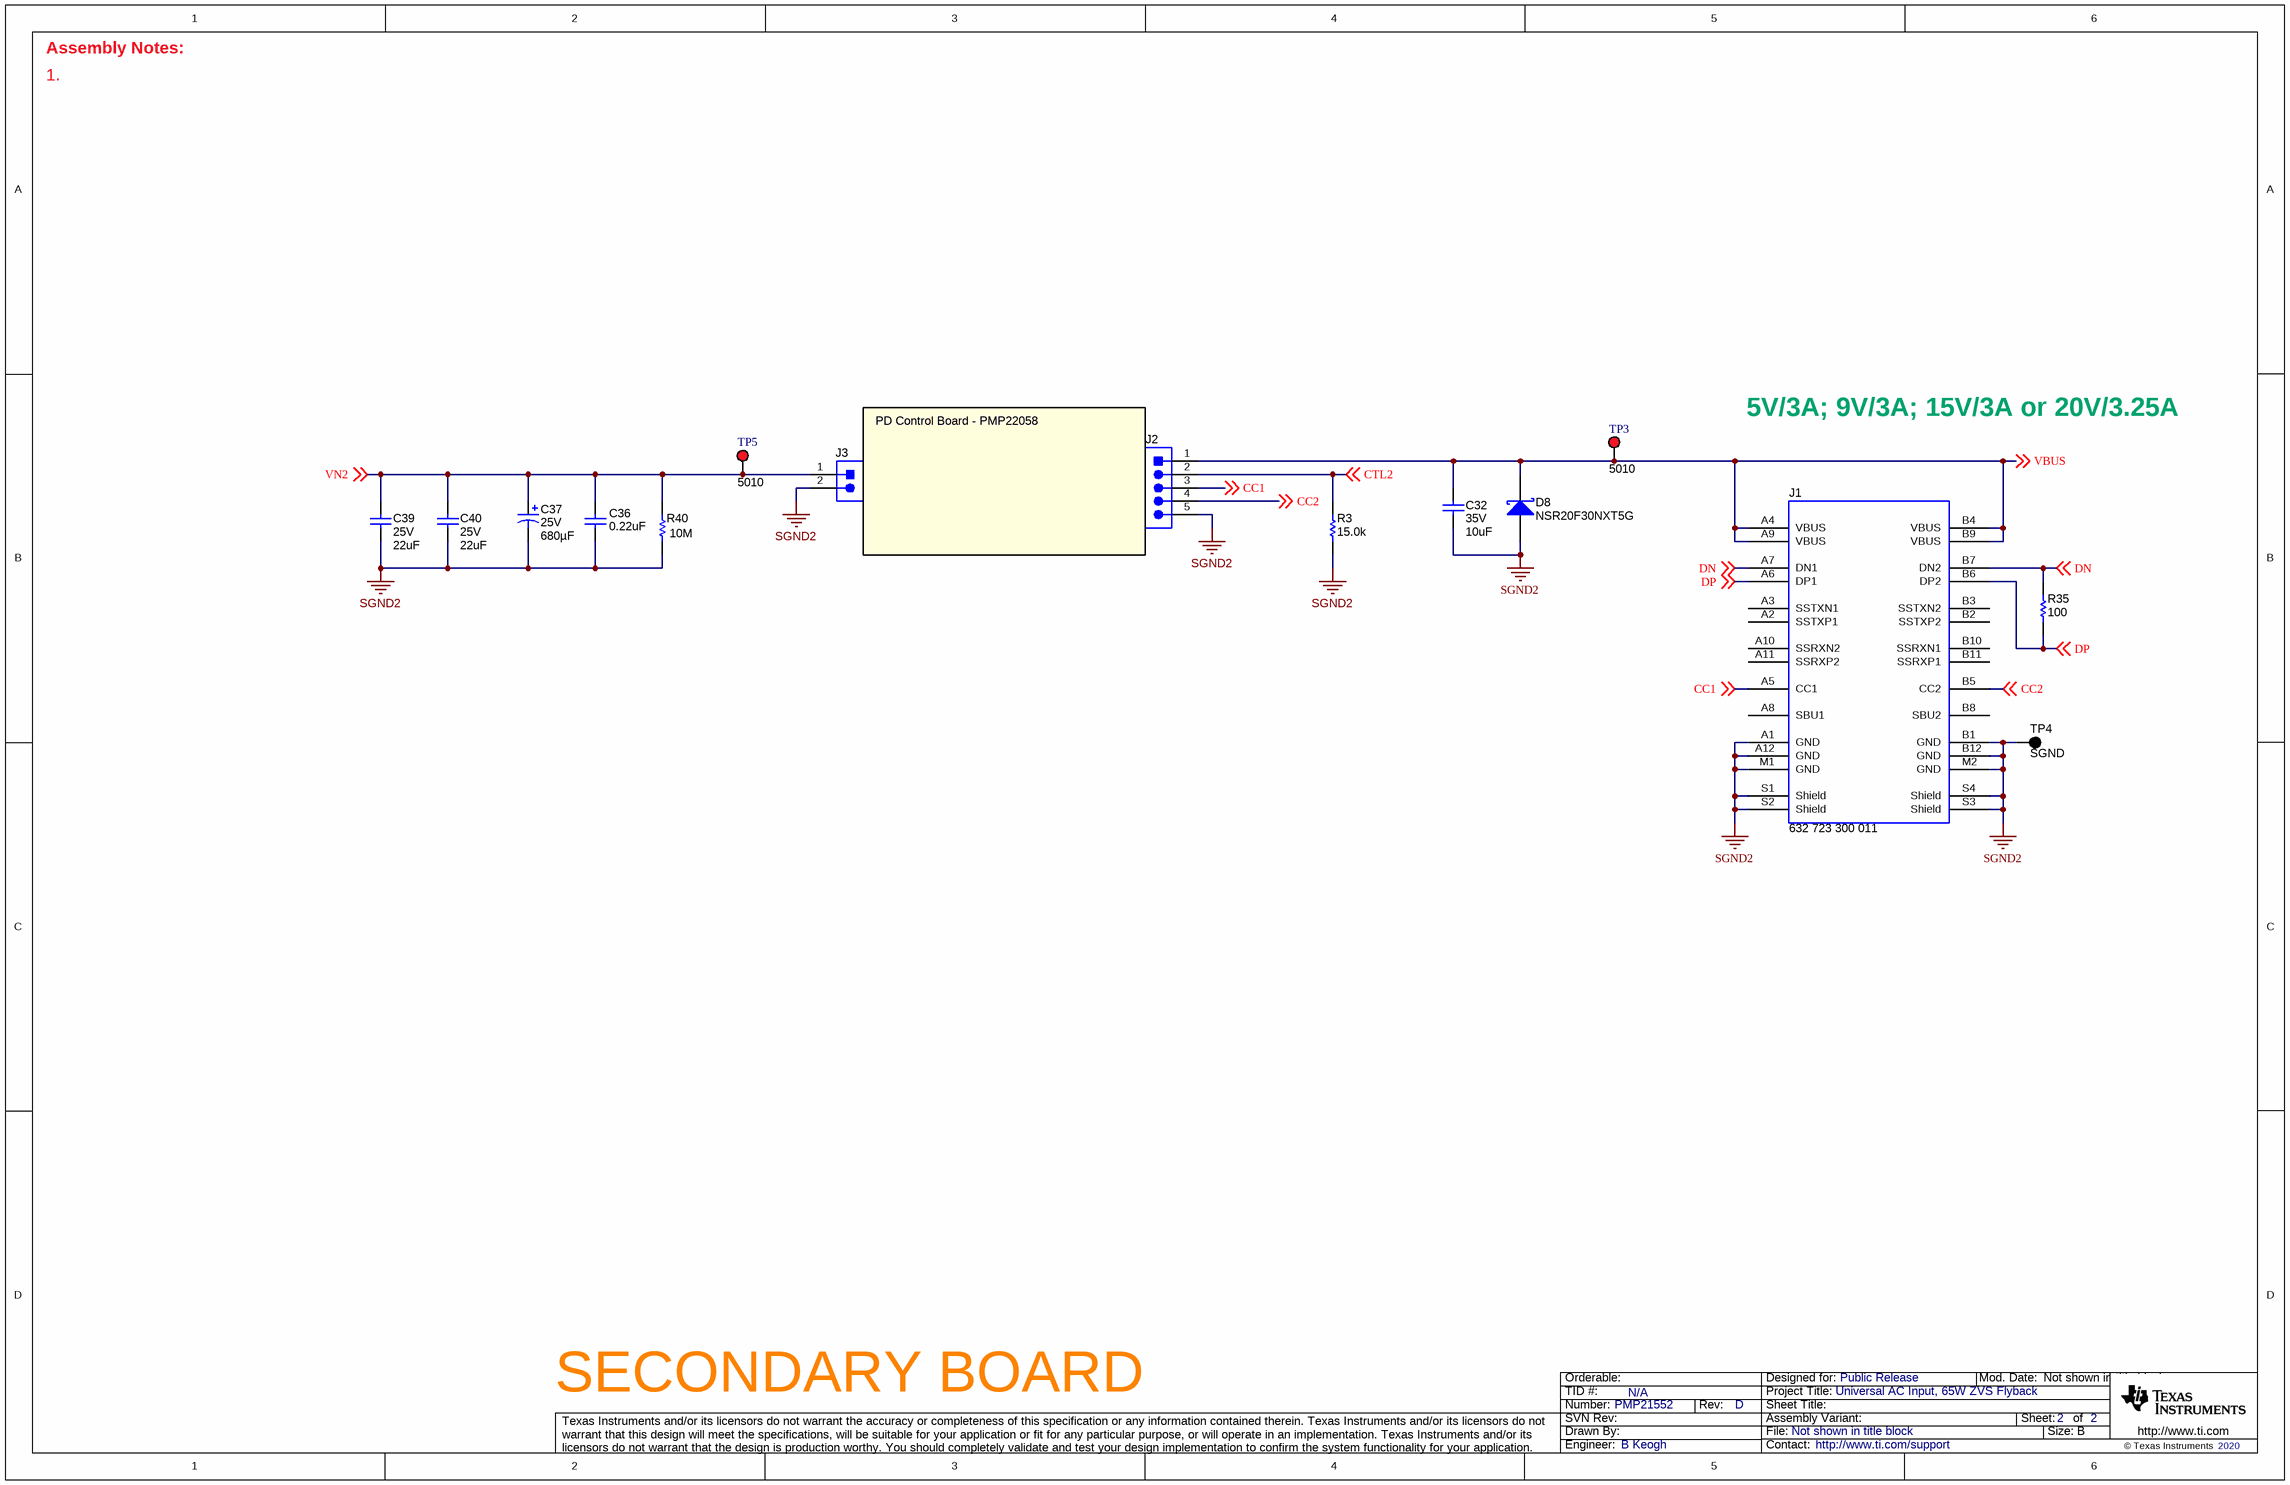
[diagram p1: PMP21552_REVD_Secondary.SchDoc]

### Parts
C32  VDC_V: 35V  ValueDisplayed: 10uF  [0805_HV1]  (hidden comment: GRM21BR6YA106KE43L)
C36  ValueDisplayed: 0.22uF  [1206L]  (hidden comment: GRM31MR71H224KA01L)
C37  VDC_V: 25V  ValueDisplayed: 680µF  [AVG_1000x1200_HD]  (hidden comment: 687AVG025MGBJ)
C39  VDC_V: 25V  ValueDisplayed: 22uF  [1210_270L]  (hidden comment: GRM32ER71E226KE15L)
C40  VDC_V: 25V  ValueDisplayed: 22uF  [1210_270L]  (hidden comment: GRM32ER71E226KE15L)
D8  NSR20F30NXT5G  [DSN2_0603]
J1  632 723 300 011  [Wurth_632_723_300_011]
J2  GRPB051VWVN-RC  [Sullins_GRPB051VWVN-RC]  (value not drawn)
J3  GRPB021VWVN-RC  [Sullins_GRPB021VWVN-RC]  (value not drawn)
R3  ValueDisplayed: 15.0k  [0402S]  (hidden comment: CRCW040215K0FKED)
R35  ValueDisplayed: 100  [0402S]  (hidden comment: CRCW0402100RJNED)
R40  ValueDisplayed: 10M  [0603S]  (hidden comment: CRCW060310M0JNEA)
TP3  5010  [Keystone5010]
TP4  SGND  [Keystone5011]
TP5  5010  [Keystone5010]

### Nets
SGND2: C32.2 C36.2 C37.2(-) C39.2 C40.2 D8.2(A) J1.A1(GND) J1.A12(GND) J1.B1(GND) J1.B12(GND) J1.M1(GND) J1.M2(GND) J1.S1(Shield) J1.S2(Shield) J1.S3(Shield) J1.S4(Shield) J2.5 J3.2 R3.1 R40.1 TP4.1
CC1: J1.A5(CC1) J2.3 ; off-sheet CC1
CC2: J1.B5(CC2) J2.4 ; off-sheet CC2
CTL2: J2.2 R3.2 ; off-sheet CTL2
DN: J1.A7(DN1) J1.B7(DN2) R35.1 ; off-sheet DN
DP: J1.A6(DP1) J1.B6(DP2) R35.2 ; off-sheet DP
VBUS: C32.1 D8.1(K) J1.A4(VBUS) J1.A9(VBUS) J1.B4(VBUS) J1.B9(VBUS) J2.1 TP3.1 ; off-sheet VBUS
VN2: C36.1 C37.1(+) C39.1 C40.1 J3.1 R40.2 TP5.1 ; off-sheet VN2

Not connected (* = marked no-connect by the designer): J1 A2(SSTXP1) A3(SSTXN1) A8(SBU1) A10(SSRXN2) A11(SSRXP2) B2(SSTXP2) B3(SSTXN2) B8(SBU2) B10(SSRXN1) B11(SSRXP1)

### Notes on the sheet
- 1.
- Assembly Notes:
- PD Control Board - PMP22058
- 5V/3A; 9V/3A; 15V/3A or 20V/3.25A
- SECONDARY BOARD

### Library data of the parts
C32 = CMP-0008310-2: CAP, CERM, 10 uF, 35 V, +/- 10%, X5R, 0805; Manufacturer: MuRata; TaMin_C: -55°C; Polarized: N; SizeAreaWB_mm2: 6.75; Value1: Unknown; U/M: EA; Value: 10uF; TaMax_C: 85°C; SizeZ_mm: 1.45; SizeX_mm: 2; SizeY_mm: 1.25; Cap_Case: 0805; SizeArea_mm2: 2.5; Cap_F: 10µF; AEC Category: Q200
C36 = CMP-0008995-2: CAP, CERM, 0.22 uF, 50 V, +/- 10%, X7R, 1206; Manufacturer: MuRata; TaMin_C: -55°C; Polarized: N; SizeAreaWB_mm2: 10.92; Value1: Unknown; U/M: EA; Value: 0.22uF; TaMax_C: 125°C; SizeZ_mm: 1.35; SizeX_mm: 3.2; SizeY_mm: 1.6; Cap_Case: 1206; Value2: 50V; SizeArea_mm2: 5.12; CompType: Capacitor; Cap_F: 220nF; AEC Category: Q200
C37 = CMP-0081668-2: CAP, Aluminum Polymer, 680 µF, 25 V,+/- 20%, 0.29256 ohm, TH; Manufacturer: Illinois Capacitor; CompType: Capacitor; Cap_Case: 10x12mm; AEC Qualified: N; AEC Category: Q200; SizeArea_mm2: 100; SizeAreaWB_mm2: 144; Polarized: Y; SizeZ_mm: 13.5; SizeX_mm: 10; TaMax_C: 125°C; Value: 680uF; IRMS_A: 4.7A; TaMin_C: -55°C
C39 C40 = CMP-0009224-2: as C9 on sheet PMP21552_REVD_Primary
D8 = CMP-0028829-1: Diode, Schottky, 30 V, 2 A, 2-XFDFN; Manufacturer: ON Semiconductor; Io_A: 2A; Green_Lifecycle: Not Set; SizeAreaWB_mm2: 4.68; Vr_V: 30V; Green_REACh: Incomplete; TJmax_C: 150°C; U/M: EA; Value: 30V; SizeZ_mm: 0.31; SizeX_mm: 1.6; SizeY_mm: 0.8; Vf_V: 4.8dV; Value2: 0.48V; SizeArea_mm2: 1.28; AEC Qualified: N; AEC Category: Q101
J1 = CMP-0054818-1: Connector, Receptacle, USB Type C, R/A; Manufacturer: Wurth Elektronik; CNHeader: FALSE; Current_A: 3A; Gender: Female; Voltage_V: 5V; ContactFinish: Gold; CT: TRUE; Cert_UL: Y
J2 = CMP-0054560-1: Header, 50mil, 5x1, Gold, TH; Manufacturer: Sullins Connector Solutions; CT: FALSE; CNHeader: TRUE
J3 = CMP-0054555-1: Header, 50mil, 2x1, Gold, TH; Manufacturer: Sullins Connector Solutions; CNHeader: TRUE; Green_Lifecycle: Not Set; Green_REACh: Incomplete; CT: FALSE
R3 = CMP-0026027-3: RES, 15.0 k, 1%, 0.063 W, AEC-Q200 Grade 0, 0402; Manufacturer: Vishay-Dale; Power_W: 63mW; TempCo: 100 ppm/C; Value_Code: 15k0; Value: 15.0k; EIA_Code: E96; Res_ohm: 15k; SizeX_mm: 1; SizeY_mm: 0.5; SizeZ_mm: 0.6; Value2: 0.063W; AEC Qualified: Y; VDC_V: 50V; AEC Category: Q200; AEC Grade: 0
R35 = CRCW0402100RJNED: RES, 100, 5%, 0.063 W, 0402; Manufacturer: Vishay-Dale; CompType: Resistor; Value: 100; Value_Code: 100R; Tolerance_%: 5; Power_W: 0.063; Value2: 0.063W; VDC_V: 50; TempCo: 200 ppm/C; EIA_Code: E24; U/M: EA; AEC Category: Q200
R40 = CMP-0025702-4: RES, 10 M, 5%, 0.1 W, AEC-Q200 Grade 0, 0603; Manufacturer: Vishay-Dale; CompType: Resistor; Value: 10Meg; Value_Code: 10M0; Power_W: 100mW; Value2: 0.1W; VDC_V: 75V; TempCo: 200 ppm/C; SizeArea_mm2: 1.28; SizeX_mm: 1.6; SizeY_mm: 0.8; SizeZ_mm: 1; EIA_Code: E24; AEC Category: Q200; AEC Qualified: Y; AEC Grade: 0
TP3 TP5 = CMP-0055147-1: Test Point, Multipurpose, Red, TH; Manufacturer: Keystone; CNHeader: FALSE; Green_Lifecycle: Active; Green_REACh: Passed; ContactFinish: Silver; CT: TRUE
TP4 = CMP-0055148-1: as TP1 on sheet PMP21552_REVD_Primary

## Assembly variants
001: not fitted C20 C28 C33 D12 R3 R10 R29 R40 R41 R43 R45 R46 R47 R48 R49 R50 R53 R54 U10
